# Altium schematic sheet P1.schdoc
size 297 x 209 mm; Symbol: Drawing-Symbol_A4; Company: 嘉立创EDA; Version: V1.0; Page Size: A4; @Project Name: 远程开机卡; @Update Date: 2026-03-22; @Create Date: 2026-03-22; Device: Drawing-Symbol_A4; @Board Name: Board2; @Page Name: P1; @Create Time: 20:18:09; @Page Count: 1; @Page No: 1; @Schematic Name: Schematic2; @Update Time: 20:18:09; @Assembly Variant: Basic; Border: 1; Title Block Position: 3; Size: A4; Width: 1170; Height: 825; Region Start: 1; X Region Count: 6; Y Region Count: 4; Blade Width: 10
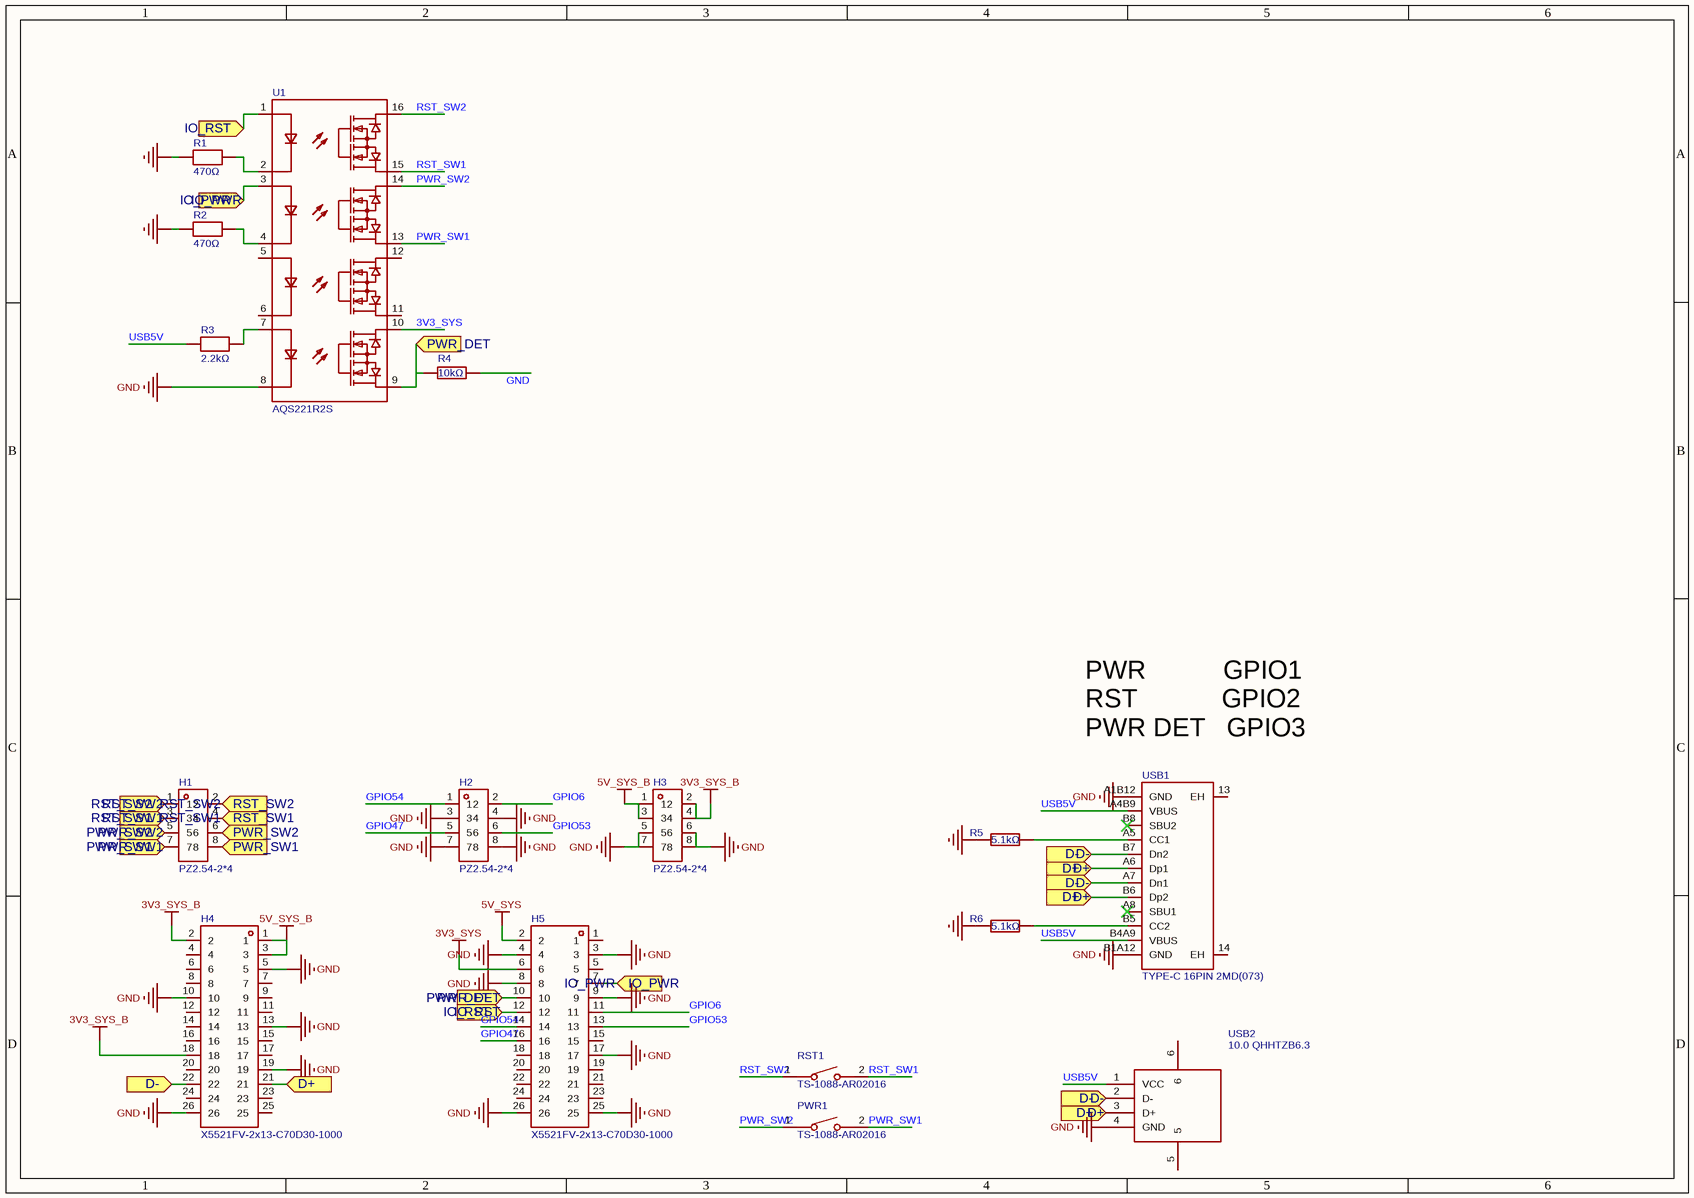
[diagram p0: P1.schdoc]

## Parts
H1  PZ2.54-2*4  [HDR-TH_8P-P2.54-V-M-R2-C4-S2.54]
H2  PZ2.54-2*4  [HDR-TH_8P-P2.54-V-M-R2-C4-S2.54]
H3  PZ2.54-2*4  [HDR-TH_8P-P2.54-V-M-R2-C4-S2.54]
H4  X5521FV-2x13-C70D30-1000  [HDR-TH_26P-P2.54-V-F-R2-C13-S2.54-3]
H5  X5521FV-2x13-C70D30-1000  [HDR-TH_26P-P2.54-V-F-R2-C13-S2.54-3]
PWR1  TS-1088-AR02016  [SW-SMD_L3.9-W3.0-P4.45]
R1  470Ω  [R0603]
R2  470Ω  [R0603]
R3  2.2kΩ  [R0603]
R4  10kΩ  [R0603]
R5  5.1kΩ  [R0603]
R6  5.1kΩ  [R0603]
RST1  TS-1088-AR02016  [SW-SMD_L3.9-W3.0-P4.45]
U1  AQS221R2S  [SO-16_L10.3-W4.4-P1.27-LS7.0-BL]
USB1  TYPE-C 16PIN 2MD(073)  [USB-C-SMD_TYPE-C-16PIN-2MD-073]
USB2  10.0 QHHTZB6.3  [USB-A-TH_10.0QHHTZB6.3]

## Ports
D+ (in), D- (in), IO_PWR (in), IO_RST (in), PWR_DET (in), PWR_SW1 (in), PWR_SW2 (in), RST_SW1 (in), RST_SW2 (in)

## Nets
3V3_SYS: H5.6 U1.10
3V3_SYS_B: H3.2 H3.4 H4.2 H4.18
5V_SYS: H5.2
5V_SYS_B: H3.1 H3.3 H4.1 H4.3
GND: H2.3 H2.4 H2.7 H2.8 H3.5 H3.6 H3.7 H3.8 H4.5 H4.10 H4.13 H4.19 H4.26 H5.3 H5.4 H5.8 H5.9 H5.17 H5.25 H5.26 R1.1 R2.1 R4.1 R5.1 R6.1 U1.8 USB1.A1B12(GND) USB1.B1A12(GND) USB2.4(GND)
D+: H4.21 USB1.A6(Dp1) USB1.B6(Dp2) USB2.3(D+) ; port D+
D-: H4.22 USB1.A7(Dn1) USB1.B7(Dn2) USB2.2(D-) ; port D-
GPIO6: H2.2 H5.11
GPIO47: H2.5 H5.16
GPIO53: H2.6 H5.13
GPIO54: H2.1 H5.14
IO_PWR: H5.7 U1.3 ; port IO_PWR
IO_RST: H5.12 U1.1 ; port IO_RST
PWR_DET: H5.10 R4.2 U1.9 ; port PWR_DET
PWR_SW1: H1.7 H1.8 PWR1.2 U1.13 ; port PWR_SW1
PWR_SW2: H1.5 H1.6 PWR1.1 U1.14 ; port PWR_SW2
RST_SW1: H1.3 H1.4 RST1.2 U1.15 ; port RST_SW1
RST_SW2: H1.1 H1.2 RST1.1 U1.16 ; port RST_SW2
USB5V: R3.2 USB1.A4B9(VBUS) USB1.B4A9(VBUS) USB2.1(VCC)
NetR1_2: R1.2 U1.2
NetR2_2: R2.2 U1.4
NetR3_1: R3.1 U1.7
NetR5_2: R5.2 USB1.A5(CC1)
NetR6_2: R6.2 USB1.B5(CC2)

Not connected (* = marked no-connect by the designer): H4 4 6 7 8 9 11 12 14 15 16 17 20 23 24 25; H5 1 5 15 18 19 20 21 22 23 24; U1 5 6 11 12; USB1 13(EH) 14(EH) A8(SBU1)* B8(SBU2)*; USB2 5 6

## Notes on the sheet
- (near USB1) PWR           GPIO1
  RST            GPIO2
  PWR DET   GPIO3

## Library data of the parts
H1 = PZ2.54-2*4: 插针结构:2x4P;间距:2.54mm;行距:2.54mm;圆针/方针:方针;安装方式:直插;排数:双排;总PIN位数:8P;额定电流:2.5A;配合针长度:6mm;塑高:2.54mm;端接针长度:3mm;触头材质:黄铜;触头镀层:金;工作温度:-40℃~+105℃;; Manufacturer: ZHOURI(洲日); AddInBom: yes; ModelId: 9655140a9899454ea9d6a6732d55fb0e0819f05c4eef4c71ace90d822a990e87; ModelName: HDR-TH_8P-P2.54-M-LI-2X4P; ModelTransform: 399.999,200,0,0,0,0,0,0,-118.11; Pin Structure: 2x4P; Pitch: 2.54mm; Circluar Pins/Square Pins: 方针; Current Rating: 2.5A
H2 H3 = PZ2.54-2*4: 插针结构:2x4P;间距:2.54mm;行距:2.54mm;圆针/方针:方针;安装方式:直插;排数:双排;总PIN位数:8P;额定电流:2.5A;配合针长度:6mm;塑高:2.54mm;端接针长度:3mm;触头材质:黄铜;触头镀层:金;工作温度:-40℃~+105℃;; Manufacturer: ZHOURI(洲日); 3D Model: 9655140a9899454ea9d6a6732d55fb0e0819f05c4eef4c71ace90d822a990e87; 3D Model Transform: 399.999,200,0,0,0,0,0,0,-118.11; Pin Structure: 2x4P; Pitch: 2.54mm; Circluar Pins/Square Pins: 方针; Current Rating: 2.5A; AddInBom: yes; ModelName: HDR-TH_8P-P2.54-M-LI-2X4P
H4 = X5521FV-2x13-C70D30-1000: 插孔结构:2x13P;间距:2.54mm;行距:2.54mm;圆孔/方孔:圆孔;安装方式:直插;排数:双排;总孔位数:26P;额定电流:3A;额定电压:-;插孔方向:顶部;塑高:7mm;触头材质:黄铜;触头镀层:金;工作温度:-40℃~+105℃;; Manufacturer: XKB Connection(中国星坤); AddInBom: yes; ModelId: ba388dff91ff45f4a180f16eead5546d0819f05c4eef4c71ace90d822a990e87; ModelName: HDR-TH_26P-P2.54-F-LI-2X13P-R1; ModelTransform: 1299.9974,200,0,0,0,0,0,0,-118.11; Holes Structure: 2x13P; Pitch: 2.54mm; Circular Hole / Square Hole: 圆孔; Number of Positions: 26P; Current Rating: 3A; Holes Direction: 顶部
H5 = X5521FV-2x13-C70D30-1000: 插孔结构:2x13P;间距:2.54mm;行距:2.54mm;圆孔/方孔:圆孔;安装方式:直插;排数:双排;总孔位数:26P;额定电流:3A;额定电压:-;插孔方向:顶部;塑高:7mm;触头材质:黄铜;触头镀层:金;工作温度:-40℃~+105℃;; Manufacturer: XKB Connection(中国星坤); Add into BOM: yes; 3D Model: ba388dff91ff45f4a180f16eead5546d; 3D Model Transform: 1299.9974,200,0,0,0,0,0,0,-118.11; Holes Structure: 2x13P; Pitch: 2.54mm; Circular Hole / Square Hole: 圆孔; Number of Positions: 26P; Current Rating: 3A; Holes Direction: 顶部; ModelName: HDR-TH_26P-P2.54-F-LI-2X13P-R1
PWR1 RST1 = TS-1088-AR02016: 电路结构:单刀单掷;按钮形状:圆形按钮;作用力:1.6N;安装方式:立贴;开关长度:4mm;开关宽度:3mm;开关高度:2mm;带支架:不带支架;触点电流:50mA;额定电压:12V;工作寿命:10万次;; Manufacturer: XUNPU(讯普); 3D Model: b26698b69f274ffabef8a26c7d0e5dd10819f05c4eef4c71ace90d822a990e87; 3D Model Transform: 188.976,114.174,0,0,0,0,0,0,0; Circuit: 单刀单掷; Actuator Style: 圆形按钮; Operating Force: 1.6N; Switch Height: 2mm; with Bracket: 不带支架; Contact Current: 50mA; Voltage Rating: 12V; Actuator/Cap Color: 黑色; Life: 10万次; AddInBom: yes; ModelName: SW-SMD_L3.9-W2.9-H2.0-LS4.8
R1 R2 = FRC0603J471 TS: 电阻类型:厚膜电阻;阻值:470Ω;精度:±5%;功率:100mW;工作电压:75V;温度系数:±100ppm/℃;; Manufacturer: FOJAN(富捷); Add into BOM: yes; 3D Model: fc143cca1e79419f9cd78b61e9279f08; 3D Model Transform: 31.8897,63.7794,0,90,0,0,0,0,0; Tolerance: ±5%; Power(Watts): 100mW; Voltage-Supply(Max): 75V
R3 = FRC0603F2201TS: 电阻类型:厚膜电阻;阻值:2.2kΩ;精度:±1%;功率:100mW;工作电压:75V;温度系数:±100ppm/℃;; Manufacturer: FOJAN(富捷); Add into BOM: yes; 3D Model: fc143cca1e79419f9cd78b61e9279f08; 3D Model Transform: 31.8897,63.7794,0,90,0,0,0,0,0; Tolerance: ±1%; Power(Watts): 100mW; Voltage-Supply(Max): 75V
R4 = 0603WAF1002T5E: 电阻类型:厚膜电阻;阻值:10kΩ;精度:±1%;功率:100mW;工作电压:75V;温度系数:±100ppm/℃;; Manufacturer: UNI-ROYAL(厚声); Symbol: 电阻; 3D Model: fc143cca1e79419f9cd78b61e9279f08; 3D Model Transform: 31.8897,63.7794,0,90,0,0,0,0,0; Tolerance: ±1%; Power(Watts): 100mW; Voltage-Supply(Max): 75V; AddInBom: yes
R5 R6 = FRC0402J512 TS: 电阻类型:厚膜电阻;阻值:5.1kΩ;精度:±5%;功率:62.5mW;工作电压:50V;温度系数:±100ppm/℃;; Manufacturer: FOJAN(富捷); Symbol: 电阻; Add into BOM: yes; 3D Model: 98c88bc2b9094f218f3a3e30a7012738; 3D Model Transform: 39.37,19.685,0,0,0,0,0,0,0; Tolerance: ±5%; Power(Watts): 62.5mW; Voltage-Supply(Max): 50V; ModelName: R0402_L1.0-W0.5-H0.4
U1 = AQS221R2S: Manufacturer: PANASONIC(松下); 3D Model: 3466bc42bba0413d8ed37ce37c1ae1480819f05c4eef4c71ace90d822a990e87; 3D Model Transform: 275.824,405.511,0,90,0,0,0,0,0; AddInBom: yes; ModelName: SO-16_L10.3-W4.4-H2.1-P1.27
USB1 = TYPE-C 16PIN 2MD(073): 连接器类型:Type-C;协议标准:-;公母:母;安装方式:卧贴;触点数量:16P;端口数量:1;额定电流 - 电源:3A;工作温度:-25℃~+85℃;; Manufacturer: SHOU HAN(首韩); 3D Model: 3a41b9ec9b654a0fad4d118405ec62900819f05c4eef4c71ace90d822a990e87; 3D Model Transform: 351.9678,298.4246,0,0,0,0,0,-47.244,-35.433; Gender: 母; Number of Contacts: 16P; Number of Ports: 1; Current Rating-Power: 3A; Voltage Rating: 5V; Connect-Disconnect Life: 1万次; Detection color: 黑色; AddInBom: yes; ModelName: USB-C-SMD_TYPE-C-6PIN-2MD-073
USB2 = 10.0 QHHTZB6.3: 连接器类型:Type-A;协议标准:USB 2.0;公母:母;安装方式:卧贴;触点数量:4P;端口数量:1;额定电流 - 电源:1.5A;工作温度:-25℃~+85℃;; Manufacturer: SHOU HAN(首韩); AddInBom: yes; ModelId: 1437c7885d7f4eabac3a392863c39379; ModelTransform: 570.865,448.818,0,0,0,0,0,-51.182,-78.74; Connector Type: Type-A; Protocol Standard: USB 2.0; Gender: 母; Number of Contacts: 4P; Number of Ports: 1; Current Rating-Power: 1.5A; Voltage Rating: 30V; Connect-Disconnect Life: 5千次; Detection color: 黑色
